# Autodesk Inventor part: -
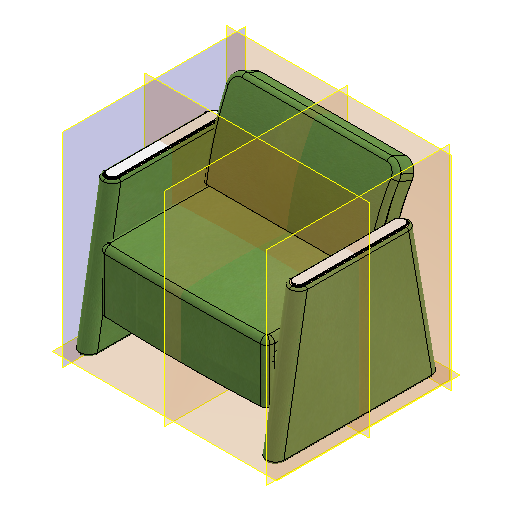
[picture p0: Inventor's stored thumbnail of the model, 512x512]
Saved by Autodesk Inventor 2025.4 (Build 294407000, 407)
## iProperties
Created: 2026-05
Part Number: -
Material: Generic
Description: BH BARIATRIC CHAIR
Document SubType Name: Modeling
Designer: Brian.Thangei
Density: 1 g/cm^3
Appearance: Default
Project: SHORE
Sending System: SolidWorks 2026
Preprocessor: SwSTEP 2.0
Title: 1301.02 - SHORE BH BARIATRIC.STEP
Revision Number: ANY
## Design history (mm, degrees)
combine "NONE"
combine "NONE:1"
combine "NONE:2"
combine "NONE:3"
combine "NONE:4"
combine "NONE:5"
combine "NONE:6"
combine "NONE:7"
combine "NONE:8"
combine "NONE:9"
combine "NONE:10"
combine "NONE:11"
combine "NONE:12"
combine "Combine1"
combine "NONE:13"
combine "Combine3"
combine "Combine4"
workplane "Work Plane1"
workplane "Work Plane2"
workplane "Work Plane3"
node "FOOT"
node "FOOT2"
node "FOOT3"
node "CORIAN"
node "FOOT4"
node "FOOT5"
node "CORIAN2"
node "ARM BASE"
node "FOOT6"
node "ARM BASE2"
node "ARM TOP"
node "ARM TOP2"
node "BASE"
node "BACK"
node "SEAT"
node "ARM"
node "ARM2"
other parameters: "d0" = 0, "d1" = 0
